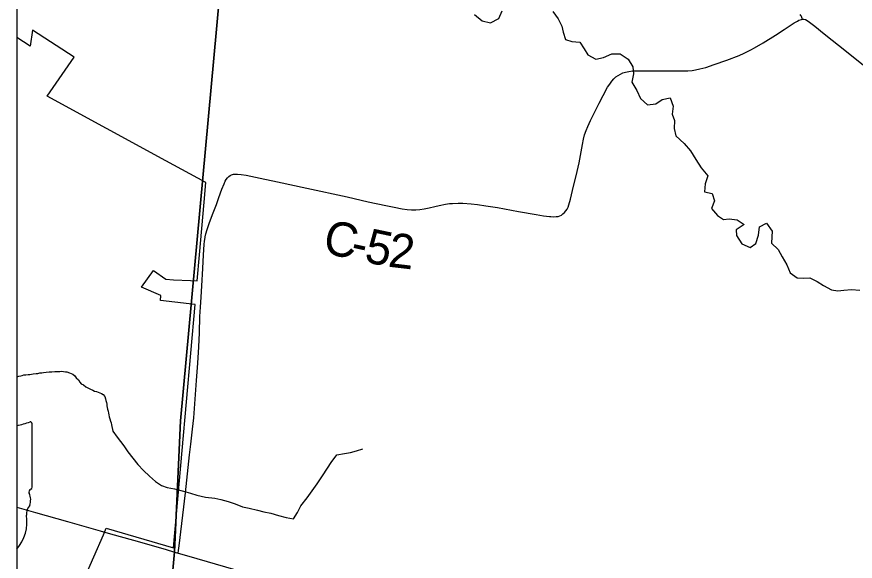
# Model space of a CAD drawing. Extents: x -1.4 to 35.4, y 0 to 22.
# Drawn here: x 2.2 to 3.586, y 14.524 to 15.424 of the extents above; entities that cross this region are included whole.
import ezdxf

# ---------------------------------------------------------------- set-up
doc = ezdxf.new("R2010")
doc.units = 0
for name, color, linetype in [('Default', 7, 'Continuous'), ('GM_X_County_Road', 7, 'Continuous'), ('GM_X_County_Road_Text', 7, 'Continuous'), ('GM_X_Interstate_Shield', 7, 'Continuous'), ('GM_X_Minor_River', 7, 'Continuous'), ('GM_X_State_Route', 7, 'Continuous'), ('GM_X_Township_Road', 7, 'Continuous'), ('SH_Border', 7, 'Continuous'), ('SH_Cut_Line', 7, 'Continuous')]:
    doc.layers.add(name, color=color, linetype=linetype)

msp = doc.modelspace()

# ---------------------------------------------------------------- linework, layer by layer
at = {"layer": 'Default'}
for points in [[(2.6843, 17.0961), (2.6688, 16.9164), (2.6641, 16.8609), (2.4708, 14.7557), (2.4607, 14.5392), (2.3914, 13.7798), (2.3288, 13.0546), (7.3379, 13.0546), (7.34, 13.0844), (7.3971, 13.8291), (7.4835, 14.4701), (7.5226, 14.9278), (7.5248, 14.9516), (7.5275, 14.9811), (7.5875, 15.692), (7.6066, 15.899), (7.693, 16.8959), (7.7561, 17.6322)], [(2.2, 17.2178), (2.2, 13.0546), (2.3288, 13.0546), (2.3914, 13.7798), (2.4607, 14.5392), (2.4708, 14.7557), (2.6641, 16.8609), (2.6688, 16.9164), (2.6843, 17.0961)], [(2.2956, 14.4581), (2.3432, 14.5673), (2.3457, 14.573), (2.3478, 14.5782), (2.4593, 14.5459), (2.4948, 14.9482), (2.485, 14.9493), (2.4379, 14.9544), (2.4382, 14.9627), (2.4065, 14.9769), (2.4262, 15.004), (2.4464, 14.9897), (2.4589, 14.9891), (2.4873, 14.9876), (2.4982, 14.987), (2.502, 15.0303), (2.5096, 15.1174), (2.5126, 15.1499), (2.4465, 15.1858), (2.2504, 15.2925), (2.2947, 15.3569), (2.2261, 15.4017), (2.2219, 15.3751), (2.2, 15.3895), (2.2, 14.4594)]]:
    msp.add_lwpolyline(points, dxfattribs=at)
at = {"layer": 'GM_X_County_Road'}
for points in [[(2.4671, 14.5368), (2.4676, 14.5415), (2.4685, 14.5492), (2.4787, 14.6367), (2.4858, 14.6996), (2.4879, 14.7169), (2.4908, 14.7422), (2.4926, 14.7607), (2.4951, 14.7916), (2.4972, 14.8226), (2.4993, 14.8511), (2.5009, 14.8783), (2.5019, 14.9013), (2.5029, 14.928), (2.5039, 14.9435), (2.505, 14.9602), (2.5062, 14.9788), (2.5075, 15.0073), (2.5085, 15.0303), (2.5097, 15.047), (2.5104, 15.0526), (2.5114, 15.0588), (2.5117, 15.06), (2.5126, 15.0647), (2.5149, 15.0718), (2.5183, 15.0822), (2.5236, 15.0968), (2.53, 15.1136), (2.534, 15.1247), (2.5393, 15.1387), (2.5427, 15.1474), (2.5448, 15.152), (2.5463, 15.1548), (2.5482, 15.1574), (2.5506, 15.1597), (2.5527, 15.1612), (2.555, 15.1624), (2.5581, 15.1634), (2.5614, 15.1638), (2.5652, 15.1638), (2.5708, 15.1632), (2.5795, 15.1617), (2.6026, 15.1568), (2.6311, 15.1506), (2.6797, 15.1402), (2.7465, 15.1258), (2.7811, 15.118), (2.8102, 15.1118), (2.8242, 15.1088), (2.837, 15.1063), (2.8455, 15.1051), (2.8529, 15.1046), (2.8596, 15.1047), (2.8664, 15.1052), (2.8737, 15.1062), (2.8816, 15.1078), (2.8912, 15.1102), (2.8985, 15.1118), (2.9089, 15.1138), (2.9157, 15.1148), (2.9206, 15.1152), (2.93, 15.1155), (2.9375, 15.1154), (2.9512, 15.1145), (2.9617, 15.1133), (2.9758, 15.1113), (2.9948, 15.1082), (3.0297, 15.102), (3.059, 15.0969), (3.0707, 15.0949), (3.0761, 15.0941), (3.081, 15.0936), (3.0829, 15.0934), (3.0871, 15.0931), (3.092, 15.0933), (3.0949, 15.0938), (3.0977, 15.0947), (3.1004, 15.096), (3.1028, 15.0977), (3.1055, 15.1001), (3.1079, 15.1028), (3.1099, 15.1058), (3.1115, 15.1091), (3.1129, 15.1131), (3.1154, 15.122), (3.1189, 15.1364), (3.1264, 15.1678), (3.1299, 15.1823), (3.1321, 15.1945), (3.1351, 15.2128), (3.1368, 15.2214), (3.1388, 15.2286), (3.1412, 15.2357), (3.144, 15.2426), (3.1486, 15.2522), (3.154, 15.2633), (3.1628, 15.2809), (3.1694, 15.2935), (3.1769, 15.3071), (3.1803, 15.3124), (3.184, 15.3174), (3.1874, 15.3212), (3.1907, 15.3242), (3.1943, 15.3268), (3.1981, 15.3291), (3.2022, 15.3309), (3.2064, 15.3323), (3.212, 15.3334), (3.2182, 15.3341), (3.2251, 15.3344), (3.2413, 15.3346), (3.2649, 15.3345), (3.2841, 15.3342), (3.299, 15.3341), (3.3095, 15.3343), (3.3169, 15.3349), (3.3223, 15.3358), (3.3295, 15.3374), (3.339, 15.3401), (3.3531, 15.3447), (3.3741, 15.3522), (3.3943, 15.3599), (3.4028, 15.3635), (3.4139, 15.369), (3.4199, 15.3722), (3.4342, 15.3807), (3.4546, 15.3936), (3.4687, 15.4028), (3.4854, 15.4136), (3.4908, 15.4167), (3.4933, 15.4179), (3.4954, 15.4188), (3.4973, 15.4195), (3.4983, 15.4198), (3.499, 15.4198)], [(3.499, 15.4198), (3.5004, 15.4198), (3.5013, 15.4197), (3.5039, 15.419), (3.5068, 15.4176), (3.5106, 15.4151), (3.5195, 15.4084), (3.5349, 15.3958), (3.5719, 15.3665), (3.5999, 15.3438)]]:
    msp.add_lwpolyline(points, dxfattribs=at)
at = {"layer": 'GM_X_Interstate_Shield'}
msp.add_line((2.2, 14.7475), (2.2, 14.5433), dxfattribs=at)
msp.add_lwpolyline([(2.2252, 14.646), (2.2252, 14.646), (2.2252, 14.646), (2.2252, 14.7509)], dxfattribs=at)
for centre, radius, start, end in [((2.1313, 15.0186), 0.2796, 284.219, 288.9065), ((2.2223, 14.7511), 0.00294, 355.0978, 97.738), ((2.2246, 14.6383), 0.00454, 107.9438, 210.337), ((2.2221, 14.6456), 0.00314, 289.604, 7.7341), ((2.1957, 14.6251), 0.0273, 340.033, 23.6496), ((2.2358, 14.6022), 0.0198, 136.8065, 186.9296), ((2.147, 14.5889), 0.0699, 319.2944, 8.9858)]:
    msp.add_arc(centre, radius, start, end, dxfattribs=at)
at = {"layer": 'GM_X_Minor_River'}
for points in [[(2.957, 15.4273), (2.9697, 15.4172), (2.9833, 15.4139), (2.9971, 15.4208), (3.0023, 15.4336)], [(3.0862, 15.4327), (3.0951, 15.4204), (3.1013, 15.4081), (3.1034, 15.3982), (3.1073, 15.386), (3.1179, 15.3827), (3.1308, 15.3817), (3.1381, 15.3705), (3.144, 15.3609), (3.1572, 15.3538), (3.1701, 15.3562), (3.1839, 15.3624), (3.1976, 15.3625), (3.2107, 15.3535), (3.2184, 15.3412), (3.2197, 15.3294), (3.2168, 15.3154), (3.2252, 15.302), (3.231, 15.2886), (3.2426, 15.2781), (3.2567, 15.2797), (3.2671, 15.2871), (3.2804, 15.2899), (3.2855, 15.2761), (3.2837, 15.2625), (3.2873, 15.2525), (3.287, 15.2389), (3.2898, 15.2267), (3.3036, 15.2142), (3.314, 15.2019), (3.3228, 15.1876), (3.3313, 15.1738), (3.3424, 15.1607), (3.338, 15.1475), (3.3369, 15.1342), (3.3498, 15.1317), (3.3537, 15.1194), (3.3485, 15.1066), (3.3586, 15.095), (3.3683, 15.0888), (3.3778, 15.0897), (3.3911, 15.0879), (3.4027, 15.0805), (3.3896, 15.0716), (3.3902, 15.0621), (3.3986, 15.0483), (3.4126, 15.0423), (3.4222, 15.049), (3.4266, 15.0625), (3.428, 15.0762), (3.4396, 15.0824), (3.4492, 15.0693), (3.4486, 15.0598), (3.448, 15.0496), (3.4588, 15.0391), (3.4654, 15.0268), (3.4731, 15.0134), (3.4786, 15.0004), (3.4902, 14.9922), (3.5008, 14.9916), (3.511, 14.9921), (3.5234, 14.9862), (3.5339, 14.9795), (3.5471, 14.9724), (3.5573, 14.9707), (3.5676, 14.9717), (3.5801, 14.9729), (3.5938, 14.9715)], [(2.2, 14.8285), (2.2007, 14.8287), (2.2034, 14.8294), (2.2065, 14.8301), (2.2091, 14.8308), (2.2118, 14.8316), (2.2149, 14.8315), (2.2191, 14.8322), (2.2217, 14.8325), (2.2244, 14.8329), (2.2271, 14.8332), (2.232, 14.8339), (2.2351, 14.8342), (2.2381, 14.8349), (2.2412, 14.8353), (2.2442, 14.8356), (2.2488, 14.8363), (2.2534, 14.8366), (2.2579, 14.8369), (2.2629, 14.8372), (2.2659, 14.8372), (2.2686, 14.8375), (2.2713, 14.8375), (2.2743, 14.8378), (2.2773, 14.8374), (2.2804, 14.8369), (2.283, 14.8365), (2.2872, 14.8353), (2.2899, 14.8341), (2.2925, 14.8326), (2.2959, 14.8302), (2.2981, 14.8268), (2.3019, 14.8233), (2.3041, 14.8195), (2.3067, 14.8168), (2.3101, 14.8152), (2.3142, 14.8121), (2.3173, 14.8102), (2.3218, 14.8078), (2.3256, 14.8062), (2.3286, 14.805), (2.332, 14.8042), (2.3346, 14.803), (2.3373, 14.8019), (2.3399, 14.8007), (2.343, 14.7991), (2.3456, 14.7957), (2.3467, 14.7922), (2.3474, 14.7896), (2.3485, 14.7861), (2.3488, 14.7834), (2.3491, 14.7804), (2.3495, 14.7777), (2.3502, 14.7751), (2.3509, 14.7716), (2.3516, 14.7686), (2.3523, 14.7655), (2.3527, 14.7621), (2.3537, 14.7591), (2.3548, 14.7552), (2.3559, 14.7522), (2.3566, 14.7491)], [(2.3566, 14.7491), (2.3591, 14.7385), (2.3661, 14.7289), (2.3768, 14.7146), (2.3838, 14.7046), (2.3919, 14.6942), (2.4001, 14.6834), (2.4097, 14.6737), (2.4197, 14.6641), (2.4294, 14.6555), (2.4391, 14.6489), (2.4489, 14.6456), (2.4608, 14.6431)], [(2.4608, 14.6431), (2.4757, 14.6395), (2.4873, 14.6362), (2.4975, 14.633), (2.5118, 14.6297), (2.5277, 14.6278), (2.5375, 14.6254), (2.5496, 14.6221), (2.5612, 14.6184), (2.5732, 14.6136), (2.5842, 14.6112), (2.5978, 14.6082), (2.6087, 14.6054), (2.62, 14.6032), (2.6328, 14.5992), (2.6452, 14.5959), (2.6573, 14.5938), (2.664, 14.6039), (2.6699, 14.6152), (2.6804, 14.6282), (2.6882, 14.6398), (2.6964, 14.6514), (2.7054, 14.6649), (2.7136, 14.6773), (2.7199, 14.687), (2.7292, 14.6993), (2.7421, 14.7017), (2.752, 14.7034), (2.7619, 14.7063), (2.7722, 14.7095)]]:
    msp.add_lwpolyline(points, dxfattribs=at)
at = {"layer": 'GM_X_State_Route'}
for points in [[(2.2, 14.6129), (2.2311, 14.604), (2.284, 14.5892), (2.3379, 14.574), (2.3552, 14.5691)], [(2.3552, 14.5691), (2.3929, 14.5584), (2.4456, 14.5433), (2.4609, 14.5386)], [(2.4609, 14.5386), (2.4671, 14.5368), (2.4844, 14.5317), (2.5583, 14.5104)]]:
    msp.add_lwpolyline(points, dxfattribs=at)
at = {"layer": 'GM_X_Township_Road'}
msp.add_lwpolyline([(3.499, 15.4198), (3.4987, 15.4207), (3.4981, 15.4227), (3.4975, 15.4242), (3.4969, 15.4252), (3.4963, 15.4261), (3.4951, 15.4277)], dxfattribs=at)
at = {"layer": 'SH_Border'}
msp.add_lwpolyline([(9, 19.8546), (2.2, 19.8546), (2.2, 13.0546), (9, 13.0546)], close=True, dxfattribs=at)
at = {"layer": 'SH_Cut_Line'}
msp.add_lwpolyline([(2.2, 19.619), (2.2, 13.0546), (2.3288, 13.0546), (2.3914, 13.7798), (2.4607, 14.5392), (2.4708, 14.7557), (2.6641, 16.8609), (2.6688, 16.9164), (2.6843, 17.0961), (2.6906, 17.1666), (2.7006, 17.2849), (2.7033, 17.3163), (2.7066, 17.3545), (2.7109, 17.4025), (2.7172, 17.4718), (2.7365, 17.7956), (2.7894, 18.3098), (2.9037, 19.5459), (2.4279, 19.5993), (2.3668, 19.6046)], close=True, dxfattribs=at)
msp.add_lwpolyline([(2.6843, 17.0961), (2.6688, 16.9164), (2.6641, 16.8609), (2.4708, 14.7557), (2.4607, 14.5392), (2.3914, 13.7798), (2.3288, 13.0546), (9, 13.0546), (9, 18.9633)], dxfattribs=at)

# ---------------------------------------------------------------- texts
at = {"layer": 'GM_X_County_Road_Text'}
for s, rotation, p in [('C', 347.6892, (2.7039, 15.0339)), ('5', 348.1216, (2.7728, 15.0189)), ('2', 353.2548, (2.8125, 15.0108)), ('-', 347.765, (2.7496, 15.024))]:
    msp.add_text(s, height=0.0568, rotation=rotation, dxfattribs=at).set_placement(p)

doc.saveas('drawing.dxf')
